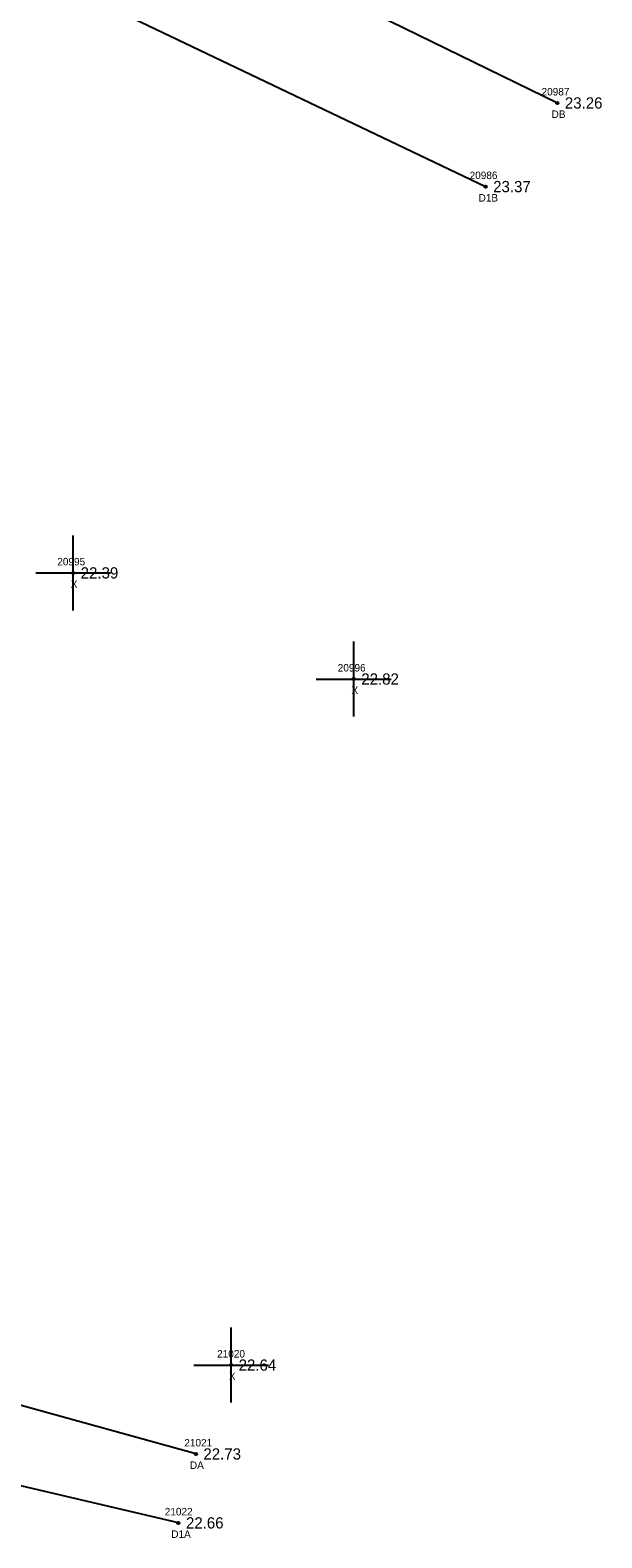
# Model space of a CAD drawing. Extents: x 2655177 to 2656219, y 761780 to 764748.
# Drawn here: x 2655596.2 to 2655672.5, y 762373.8 to 762575 of the extents above; entities that cross this region are included whole.
import ezdxf

# ---------------------------------------------------------------- set-up
doc = ezdxf.new("R2010")
doc.units = 0
for name, color, linetype in [('RD_EX_Driveway', 7, 'Continuous'), ('RD_EX_Driveway_txCode', 7, 'Continuous'), ('RD_EX_Misc', 7, 'Continuous'), ('RD_EX_Misc_txCode', 7, 'Continuous'), ('RD_EX_TX_Driveway_ELEV', 7, 'Continuous'), ('RD_EX_TX_Misc_ELEV', 7, 'Continuous'), ('RD_SMD_Locator', 7, 'Continuous')]:
    doc.layers.add(name, color=color, linetype=linetype)

msp = doc.modelspace()

# ---------------------------------------------------------------- linework, layer by layer
at = {"layer": 'RD_EX_Driveway'}
for points in [[(2655592.52, 762601.16), (2655603.35, 762596.15), (2655666.52, 762565.25)], [(2655588.62, 762587.62), (2655600.18, 762581.22), (2655656.95, 762554.09)], [(2655618.28, 762384.97), (2655560.02, 762401.08), (2655544.59, 762408.15)], [(2655615.95, 762375.77), (2655557.51, 762389.46), (2655538.99, 762389.2)]]:
    msp.add_lwpolyline(points, dxfattribs=at)
at = {"layer": 'RD_EX_Misc'}
for p, q in [((2655601.9, 762497.54), (2655601.9, 762507.54)), ((2655596.9, 762502.54), (2655606.9, 762502.54)), ((2655639.35, 762483.38), (2655639.35, 762493.38)), ((2655634.35, 762488.38), (2655644.35, 762488.38)), ((2655622.98, 762391.83), (2655622.98, 762401.83)), ((2655617.98, 762396.83), (2655627.98, 762396.83))]:
    msp.add_line(p, q, dxfattribs=at)
at = {"layer": 'RD_SMD_Locator'}
for centre in [(2655666.52, 762565.25), (2655656.95, 762554.09), (2655601.9, 762502.54), (2655639.35, 762488.38), (2655622.98, 762396.83), (2655618.28, 762384.97), (2655615.95, 762375.77)]:
    msp.add_circle(centre, 0.15, dxfattribs=at)

# ---------------------------------------------------------------- texts
at = {"layer": 'RD_EX_Driveway_txCode'}
for s, p in [('20987', (2655664.41, 762566.25)), ('DB', (2655665.75, 762563.25)), ('20986', (2655654.81, 762555.09)), ('D1B', (2655656, 762552.09)), ('21021', (2655616.73, 762385.97)), ('DA', (2655617.48, 762382.97)), ('21022', (2655614.12, 762376.77)), ('D1A', (2655614.99, 762373.77))]:
    msp.add_text(s, height=1, dxfattribs=at).set_placement(p)
at = {"layer": 'RD_EX_Misc_txCode'}
for s, p in [('20995', (2655599.78, 762503.54)), ('X', (2655601.58, 762500.54)), ('20996', (2655637.21, 762489.38)), ('X', (2655639.04, 762486.38)), ('21020', (2655621.11, 762397.83)), ('X', (2655622.67, 762394.83))]:
    msp.add_text(s, height=1, dxfattribs=at).set_placement(p)
at = {"layer": 'RD_EX_TX_Driveway_ELEV'}
for s, p in [('23.26', (2655667.52, 762564.5)), ('23.37', (2655657.95, 762553.34)), ('22.73', (2655619.28, 762384.22)), ('22.66', (2655616.95, 762375.02))]:
    msp.add_text(s, height=1.5, dxfattribs=at).set_placement(p)
at = {"layer": 'RD_EX_TX_Misc_ELEV'}
for s, p in [('22.39', (2655602.9, 762501.79)), ('22.82', (2655640.35, 762487.63)), ('22.64', (2655623.98, 762396.08))]:
    msp.add_text(s, height=1.5, dxfattribs=at).set_placement(p)

doc.saveas('drawing.dxf')
